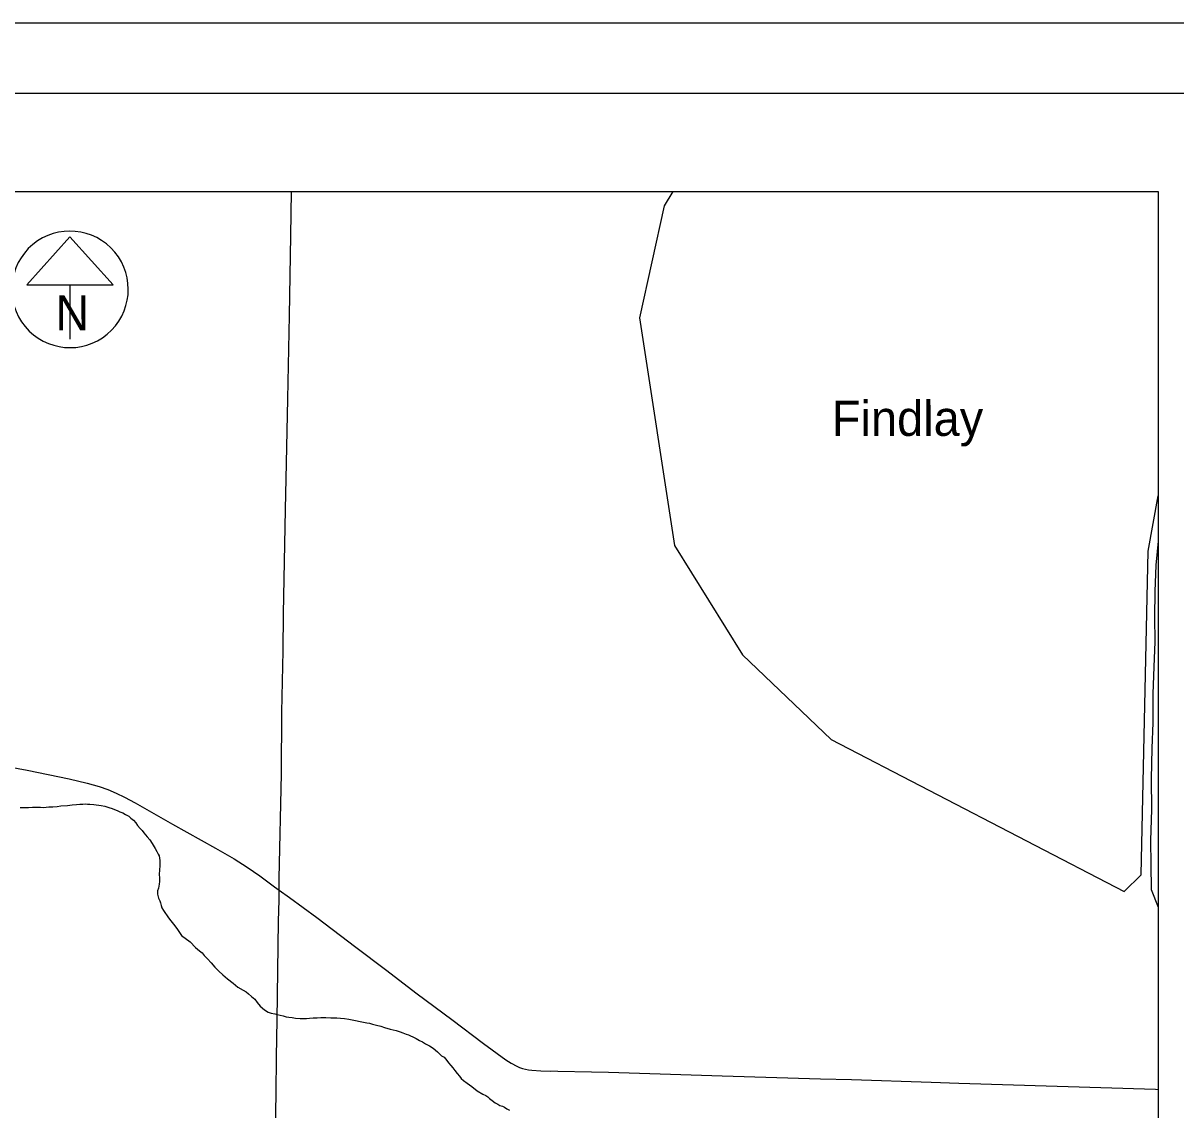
# Model space of a CAD drawing. Extents: x 1 to 1971, y -2 to 1107.
# Drawn here: x 1664.12 to 1672.33, y 1098.86 to 1106.6 of the extents above; entities that cross this region are included whole.
import ezdxf

# ---------------------------------------------------------------- set-up
doc = ezdxf.new("R2010")
doc.units = 0
for name, color, linetype in [('GM_X_Major_Lake_Text', 7, 'Continuous'), ('GM_X_Minor_River', 7, 'Continuous'), ('GM_X_Township_Road', 7, 'Continuous'), ('SH_Border', 7, 'Continuous'), ('SH_Cut_Line', 7, 'Continuous'), ('SH_Data', 7, 'Continuous')]:
    doc.layers.add(name, color=color, linetype=linetype)

msp = doc.modelspace()

# ---------------------------------------------------------------- linework, layer by layer
at = {"layer": 'GM_X_Minor_River'}
for points in [[(1668.7474, 1105.4005), (1668.6863, 1105.2991), (1668.5097, 1104.5032), (1668.7578, 1102.882), (1669.2422, 1102.1042), (1669.8738, 1101.5012), (1671.9603, 1100.4184), (1672.08, 1100.5373), (1672.1305, 1102.8403), (1672.2022, 1103.2358)], [(1672.2022, 1102.918), (1672.2008, 1102.9132), (1672.1853, 1102.742), (1672.1776, 1102.5546), (1672.1753, 1102.3725), (1672.1785, 1102.1956), (1672.171, 1102.0189), (1672.1632, 1101.8262), (1672.1634, 1101.6199), (1672.1558, 1101.4379), (1672.1504, 1101.2183), (1672.1531, 1101.0013), (1672.1477, 1100.7817), (1672.1483, 1100.6102), (1672.1515, 1100.4334), (1672.2022, 1100.3073)], [(1664.1017, 1101.0171), (1664.1339, 1101.0167), (1664.1607, 1101.0163), (1664.1903, 1101.0186), (1664.2198, 1101.0182), (1664.2467, 1101.0179), (1664.2682, 1101.0176), (1664.287, 1101.0201), (1664.3058, 1101.0225), (1664.3354, 1101.0221), (1664.3649, 1101.0244), (1664.3918, 1101.0294), (1664.4375, 1101.0315), (1664.4725, 1101.0364), (1664.5021, 1101.0387), (1664.5263, 1101.041), (1664.5477, 1101.0407), (1664.5639, 1101.0432), (1664.58, 1101.0403), (1664.5988, 1101.0401), (1664.6256, 1101.037), (1664.6792, 1101.031), (1664.7033, 1101.0253), (1664.7328, 1101.0169), (1664.7568, 1101.0085), (1664.7729, 1101.003), (1664.7916, 1100.9947), (1664.8103, 1100.9864), (1664.8316, 1100.9781), (1664.8503, 1100.9671), (1664.8743, 1100.9561), (1664.8902, 1100.9398), (1664.9089, 1100.9262), (1664.9247, 1100.9072), (1664.9379, 1100.8883), (1664.9565, 1100.8666), (1664.9697, 1100.853), (1664.9829, 1100.8368), (1664.9935, 1100.8233), (1665.0067, 1100.807), (1665.0253, 1100.7854), (1665.0411, 1100.761), (1665.0621, 1100.7259), (1665.0753, 1100.7043), (1665.0831, 1100.6855), (1665.091, 1100.672), (1665.0935, 1100.6559), (1665.0959, 1100.6398), (1665.0957, 1100.6237), (1665.0955, 1100.6023), (1665.0924, 1100.5729), (1665.092, 1100.5407), (1665.0944, 1100.5166), (1665.0941, 1100.4898), (1665.0911, 1100.4711), (1665.0854, 1100.4417), (1665.0798, 1100.423), (1665.0795, 1100.3989), (1665.0872, 1100.372), (1665.095, 1100.3532), (1665.1002, 1100.337), (1665.1053, 1100.3182), (1665.1105, 1100.3021), (1665.121, 1100.2832), (1665.1579, 1100.2318), (1665.1738, 1100.2102), (1665.1923, 1100.1858), (1665.2161, 1100.156), (1665.2503, 1100.1047), (1665.3115, 1100.061), (1665.3486, 1100.0204), (1665.3779, 1099.9959), (1665.3965, 1099.9822), (1665.4124, 1099.9633), (1665.4362, 1099.9389), (1665.4601, 1099.9118), (1665.4865, 1099.8793), (1665.5157, 1099.8521), (1665.5449, 1099.8249), (1665.5768, 1099.7977), (1665.6167, 1099.7651), (1665.6512, 1099.7378), (1665.6885, 1099.7159), (1665.7099, 1099.7049), (1665.7258, 1099.6913), (1665.7471, 1099.6723), (1665.771, 1099.6532), (1665.7895, 1099.6289), (1665.8107, 1099.6018), (1665.8399, 1099.5773), (1665.8665, 1099.5609), (1665.8879, 1099.5526), (1665.9147, 1099.5469), (1665.9308, 1099.544)], [(1665.9308, 1099.544), (1665.9522, 1099.5383), (1665.9736, 1099.5327), (1665.995, 1099.527), (1666.0138, 1099.5241), (1666.0379, 1099.5211), (1666.062, 1099.5181), (1666.0942, 1099.515), (1666.1211, 1099.5147), (1666.1399, 1099.5144), (1666.1614, 1099.5168), (1666.1883, 1099.5192), (1666.2151, 1099.5188), (1666.242, 1099.5211), (1666.2769, 1099.5207), (1666.3118, 1099.5202), (1666.3333, 1099.5199), (1666.3548, 1099.5197), (1666.3816, 1099.5166), (1666.4111, 1099.5136), (1666.4406, 1099.5105), (1666.5692, 1099.4847), (1666.5879, 1099.4818), (1666.6093, 1099.4735), (1666.6388, 1099.4677), (1666.6682, 1099.4593), (1666.695, 1099.4509), (1666.7351, 1099.4397), (1666.7779, 1099.4284), (1666.8074, 1099.42), (1666.8261, 1099.4117), (1666.8501, 1099.4033), (1666.8662, 1099.3978), (1666.8795, 1099.3922), (1666.8956, 1099.384), (1666.9196, 1099.3729), (1666.9436, 1099.3593), (1666.9649, 1099.3483), (1666.9863, 1099.3346), (1667.0156, 1099.3208), (1667.0423, 1099.3044), (1667.0715, 1099.2772), (1667.1007, 1099.25), (1667.1193, 1099.2391), (1667.1378, 1099.2147), (1667.151, 1099.1985), (1667.1669, 1099.1795), (1667.1801, 1099.1633), (1667.196, 1099.1443), (1667.2119, 1099.1227), (1667.2277, 1099.1037), (1667.241, 1099.0875), (1667.2569, 1099.0739), (1667.2835, 1099.0548), (1667.3154, 1099.0302), (1667.3553, 1099.0003), (1667.3953, 1098.9756), (1667.4167, 1098.9673), (1667.43, 1098.9564), (1667.4433, 1098.9455), (1667.4619, 1098.9319), (1667.4832, 1098.9155), (1667.5018, 1098.9046), (1667.5152, 1098.8964), (1667.5339, 1098.8908), (1667.5499, 1098.8825), (1667.5659, 1098.8716), (1667.5846, 1098.8633)]]:
    msp.add_lwpolyline(points, dxfattribs=at)
at = {"layer": 'GM_X_Township_Road'}
for points in [[(1665.9448, 1100.4293), (1665.945, 1100.5124), (1665.9606, 1101.2565), (1665.9647, 1101.6943), (1665.9735, 1102.132), (1665.9767, 1102.3948), (1665.9902, 1103.1389), (1665.9974, 1103.4671), (1666.0058, 1103.9268), (1666.0181, 1104.5177), (1666.0282, 1105.0868), (1666.0339, 1105.4005)], [(1665.9448, 1100.4293), (1665.945, 1100.5124), (1665.9606, 1101.2565), (1665.9647, 1101.6943), (1665.9735, 1102.132), (1665.9767, 1102.3948), (1665.9902, 1103.1389), (1665.9974, 1103.4671), (1666.0058, 1103.9268), (1666.0181, 1104.5177), (1666.0282, 1105.0868), (1666.0339, 1105.4005)], [(1663.9583, 1101.3175), (1664.1517, 1101.2814), (1664.4517, 1101.22), (1664.5792, 1101.1894), (1664.6631, 1101.1657), (1664.7248, 1101.1448), (1664.785, 1101.1198), (1664.8438, 1101.0913), (1664.9206, 1101.0498), (1665.1868, 1100.8983), (1665.4927, 1100.7281), (1665.6245, 1100.6505), (1665.7167, 1100.5921), (1665.8066, 1100.5302), (1665.9127, 1100.4531), (1665.9448, 1100.4293)], [(1663.9583, 1101.3175), (1664.1517, 1101.2814), (1664.4517, 1101.22), (1664.5792, 1101.1894), (1664.6631, 1101.1657), (1664.7248, 1101.1448), (1664.785, 1101.1198), (1664.8438, 1101.0913), (1664.9206, 1101.0498), (1665.1868, 1100.8983), (1665.4927, 1100.7281), (1665.6245, 1100.6505), (1665.7167, 1100.5921), (1665.8066, 1100.5302), (1665.9127, 1100.4531), (1665.9448, 1100.4293)], [(1665.8647, 1095.6018), (1665.8652, 1095.6384), (1665.8691, 1095.9598), (1665.8824, 1096.7478), (1665.891, 1097.2512), (1665.9023, 1097.8203), (1665.9237, 1098.9803), (1665.9265, 1099.243), (1665.9316, 1099.5056), (1665.9414, 1100.206), (1665.9454, 1100.3592), (1665.9448, 1100.4293)], [(1665.8647, 1095.6018), (1665.8652, 1095.6384), (1665.8691, 1095.9598), (1665.8824, 1096.7478), (1665.891, 1097.2512), (1665.9023, 1097.8203), (1665.9237, 1098.9803), (1665.9265, 1099.243), (1665.9316, 1099.5056), (1665.9414, 1100.206), (1665.9454, 1100.3592), (1665.9448, 1100.4293)], [(1665.9448, 1100.4293), (1666.0184, 1100.3751), (1666.2125, 1100.233), (1666.4914, 1100.0215), (1666.7014, 1099.8638), (1666.9271, 1099.6908), (1667.1733, 1099.5083), (1667.4005, 1099.3373), (1667.5592, 1099.2201), (1667.5964, 1099.1962), (1667.6357, 1099.1755), (1667.6562, 1099.1669), (1667.6773, 1099.1594), (1667.6988, 1099.1537), (1667.7205, 1099.1492), (1667.7425, 1099.1461), (1667.8086, 1099.1416), (1667.8763, 1099.1402)], [(1665.9448, 1100.4293), (1666.0184, 1100.3751), (1666.2125, 1100.233), (1666.4914, 1100.0215), (1666.7014, 1099.8638), (1666.9271, 1099.6908), (1667.1733, 1099.5083), (1667.4005, 1099.3373), (1667.5592, 1099.2201), (1667.5964, 1099.1962), (1667.6357, 1099.1755), (1667.6562, 1099.1669), (1667.6773, 1099.1594), (1667.6988, 1099.1537), (1667.7205, 1099.1492), (1667.7425, 1099.1461), (1667.8086, 1099.1416), (1668.29, 1099.1318), (1669.0992, 1099.1072), (1669.799, 1099.0849), (1670.0178, 1099.0795), (1670.5854, 1099.0625), (1670.782, 1099.0555), (1672.1815, 1099.0107), (1672.2022, 1099.0101)]]:
    msp.add_lwpolyline(points, dxfattribs=at)
at = {"layer": 'SH_Border'}
msp.add_lwpolyline([(1652.9632, 1106.1005), (1684.9632, 1106.1005), (1684.9632, 1085.1005), (1652.9632, 1085.1005)], close=True, dxfattribs=at)
at = {"layer": 'SH_Cut_Line'}
msp.add_lwpolyline([(1651.4632, 1084.6005), (1685.4632, 1084.6005), (1685.4632, 1106.6005), (1651.4632, 1106.6005)], close=True, dxfattribs=at)
at = {"layer": 'SH_Data'}
for p, q in [((1664.4562, 1105.0786), (1664.1486, 1104.7374)), ((1664.7637, 1104.7374), (1664.4562, 1105.0786)), ((1664.1486, 1104.7374), (1664.7637, 1104.7374)), ((1664.4562, 1104.7374), (1664.4562, 1104.3506))]:
    msp.add_line(p, q, dxfattribs=at)
msp.add_lwpolyline([(1653.1763, 1105.4005), (1672.2022, 1105.4005), (1672.2022, 1085.8005), (1653.1763, 1085.8005)], close=True, dxfattribs=at)
msp.add_arc((1664.4562, 1104.7049), 0.4148, 129.77984, 129.76332, dxfattribs=at)

# ---------------------------------------------------------------- texts
at = {"layer": 'GM_X_Major_Lake_Text'}
msp.add_text('Findlay', height=0.25, rotation=0.02462, dxfattribs=at).set_placement((1669.8787, 1103.6617))
at = {"layer": 'SH_Data'}
msp.add_text('N', height=0.25, dxfattribs=at).set_placement((1664.3521, 1104.4135))

doc.saveas('drawing.dxf')
